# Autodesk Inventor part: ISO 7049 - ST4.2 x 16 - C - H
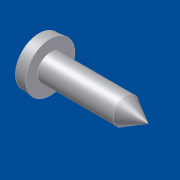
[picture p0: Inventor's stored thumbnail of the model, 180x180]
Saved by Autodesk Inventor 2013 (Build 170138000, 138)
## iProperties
Created: 2002-06
Part Number: ISO 7049 - ST4.2 x 16 - C - H
Material: Standard
Catalog Web Link: file:///D:/Programme/Inventor%205.3/Content/Din/index.htm?doNavigateId=FD02C55D-C43B-11D4-A9F1-0080AD303E0A|722B0E38B16B11D4BA6900C04F798F98|true
Description: Blechschraube
Document SubType Name: Standard Catalog Part
Standard: ISO 7049 - ST4.2 x 16 - C - H
Designer: dl
Density: 1 g/cm^3
Control State: 0
Master: False
Checked Out: False
Shininess: 20.0
Length Units: 11269
Angle Units: 11279
Time Units: 11290
Mass Units: 11283
Length Display Precision: 3
Angle Display Precision: 2
Compacted: True
KLASSIFIKATION: 31161506
HERSTELLER: DIN Normsystem
Density: 0.0
Volumn: 0.0
Area: 0.0
PropertySet Name: Model Information
Author: dl
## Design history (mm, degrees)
feature "Basis1"
body "Solid1"
